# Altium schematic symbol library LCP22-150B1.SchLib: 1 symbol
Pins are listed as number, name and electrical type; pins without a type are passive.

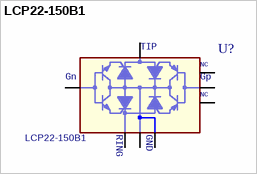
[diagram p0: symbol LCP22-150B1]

## LCP22-150B1
designator U?
footprint ST_SO8wide
pins: 1 Gn, 2 NC, 3 Gp, 4 NC1, 5 RING, 6 GND, 7 GND1, 8 TIP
